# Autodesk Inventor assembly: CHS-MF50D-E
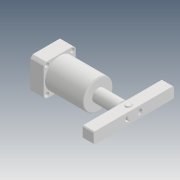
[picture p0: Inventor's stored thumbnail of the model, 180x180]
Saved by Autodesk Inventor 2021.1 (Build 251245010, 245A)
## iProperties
Created: 2019-04
Part Number: CHS-MF50D-E
Description: STEP AP203
Document SubType Name: Assembly
Designer: user
Title: chs-mf50d-e_asm.STEP
Revision Number: ÈÎºÎ
Sending System: SolidWorks 2017
Preprocessor: SwSTEP 2.0
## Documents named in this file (12)
- D:\Vault_2016\Projekty\Clamptek\Hydraulic\CHS\CHS-50\Inventor\CHS-MF50D-E\CHS-MF50D-E.iam
- D:\Vault_2016\Projekty\Clamptek\Hydraulic\CHS\CHS-50\Inventor\CHS-MF50D-E\CHS-MF50EBT_1.ipt
- D:\Vault_2016\Projekty\Clamptek\Hydraulic\CHS\CHS-50\Inventor\CHS-MF50D-E\CHS-50-EDHSG_1.ipt
- D:\Vault_2016\Projekty\Clamptek\Hydraulic\CHS\CHS-50\Inventor\CHS-MF50D-E\M6_4.ipt
- D:\Vault_2016\Projekty\Clamptek\Hydraulic\CHS\CHS-50\Inventor\CHS-MF50D-E\PRT0002_3.ipt
- D:\Vault_2016\Projekty\Clamptek\Hydraulic\CHS\CHS-50\Inventor\CHS-MF50D-E\M6LM_3.ipt
- D:\Vault_2016\Projekty\Clamptek\Hydraulic\CHS\CHS-50\Inventor\CHS-MF50D-E\PRT0003_3.ipt
- D:\Vault_2016\Projekty\Clamptek\Hydraulic\CHS\CHS-50\Inventor\CHS-MF50D-E\PRT0001_3.ipt
- D:\Vault_2016\Projekty\Clamptek\Hydraulic\CHS\CHS-50\Inventor\CHS-MF50D-E\PRT0006_3.ipt
- D:\Vault_2016\Projekty\Clamptek\Hydraulic\CHS\CHS-50\Inventor\CHS-MF50D-E\CHS-50DYB_6.ipt
- D:\Vault_2016\Projekty\Clamptek\Hydraulic\CHS\CHS-50\Inventor\CHS-MF50D-E\ÖáÓÃµ²È¦.ipt
- D:\Vault_2016\Projekty\Clamptek\Hydraulic\CHS\CHS-50\Inventor\CHS-MF50D-E\Ïú.ipt
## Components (13 placed, 13 different names)
1. CHS-MF50EBT_1_1
2. CHS-50-EDHSG_1_2
3. M6_4_3
4. M6_4_4
5. PRT0002_3_5
6. M6LM_3_6
7. PRT0003_3_7
8. PRT0001_3_8
9. PRT0006_3_9
10. CHS-50DYB_6_10
11. ÖáÓÃµ²È¦_11
12. Ïú_12
13. ÖáÓÃµ²È¦_13
